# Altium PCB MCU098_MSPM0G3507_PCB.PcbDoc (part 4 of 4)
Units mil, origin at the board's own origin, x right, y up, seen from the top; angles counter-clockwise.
Board outline 2310.03 x 4205.03 mil, 4 copper layers (Top Layer, VCC Layer, GND Layer, Bottom Layer), stack 62.4 mil thick; 260 components, 182 nets, 835 pads, 237 vias.
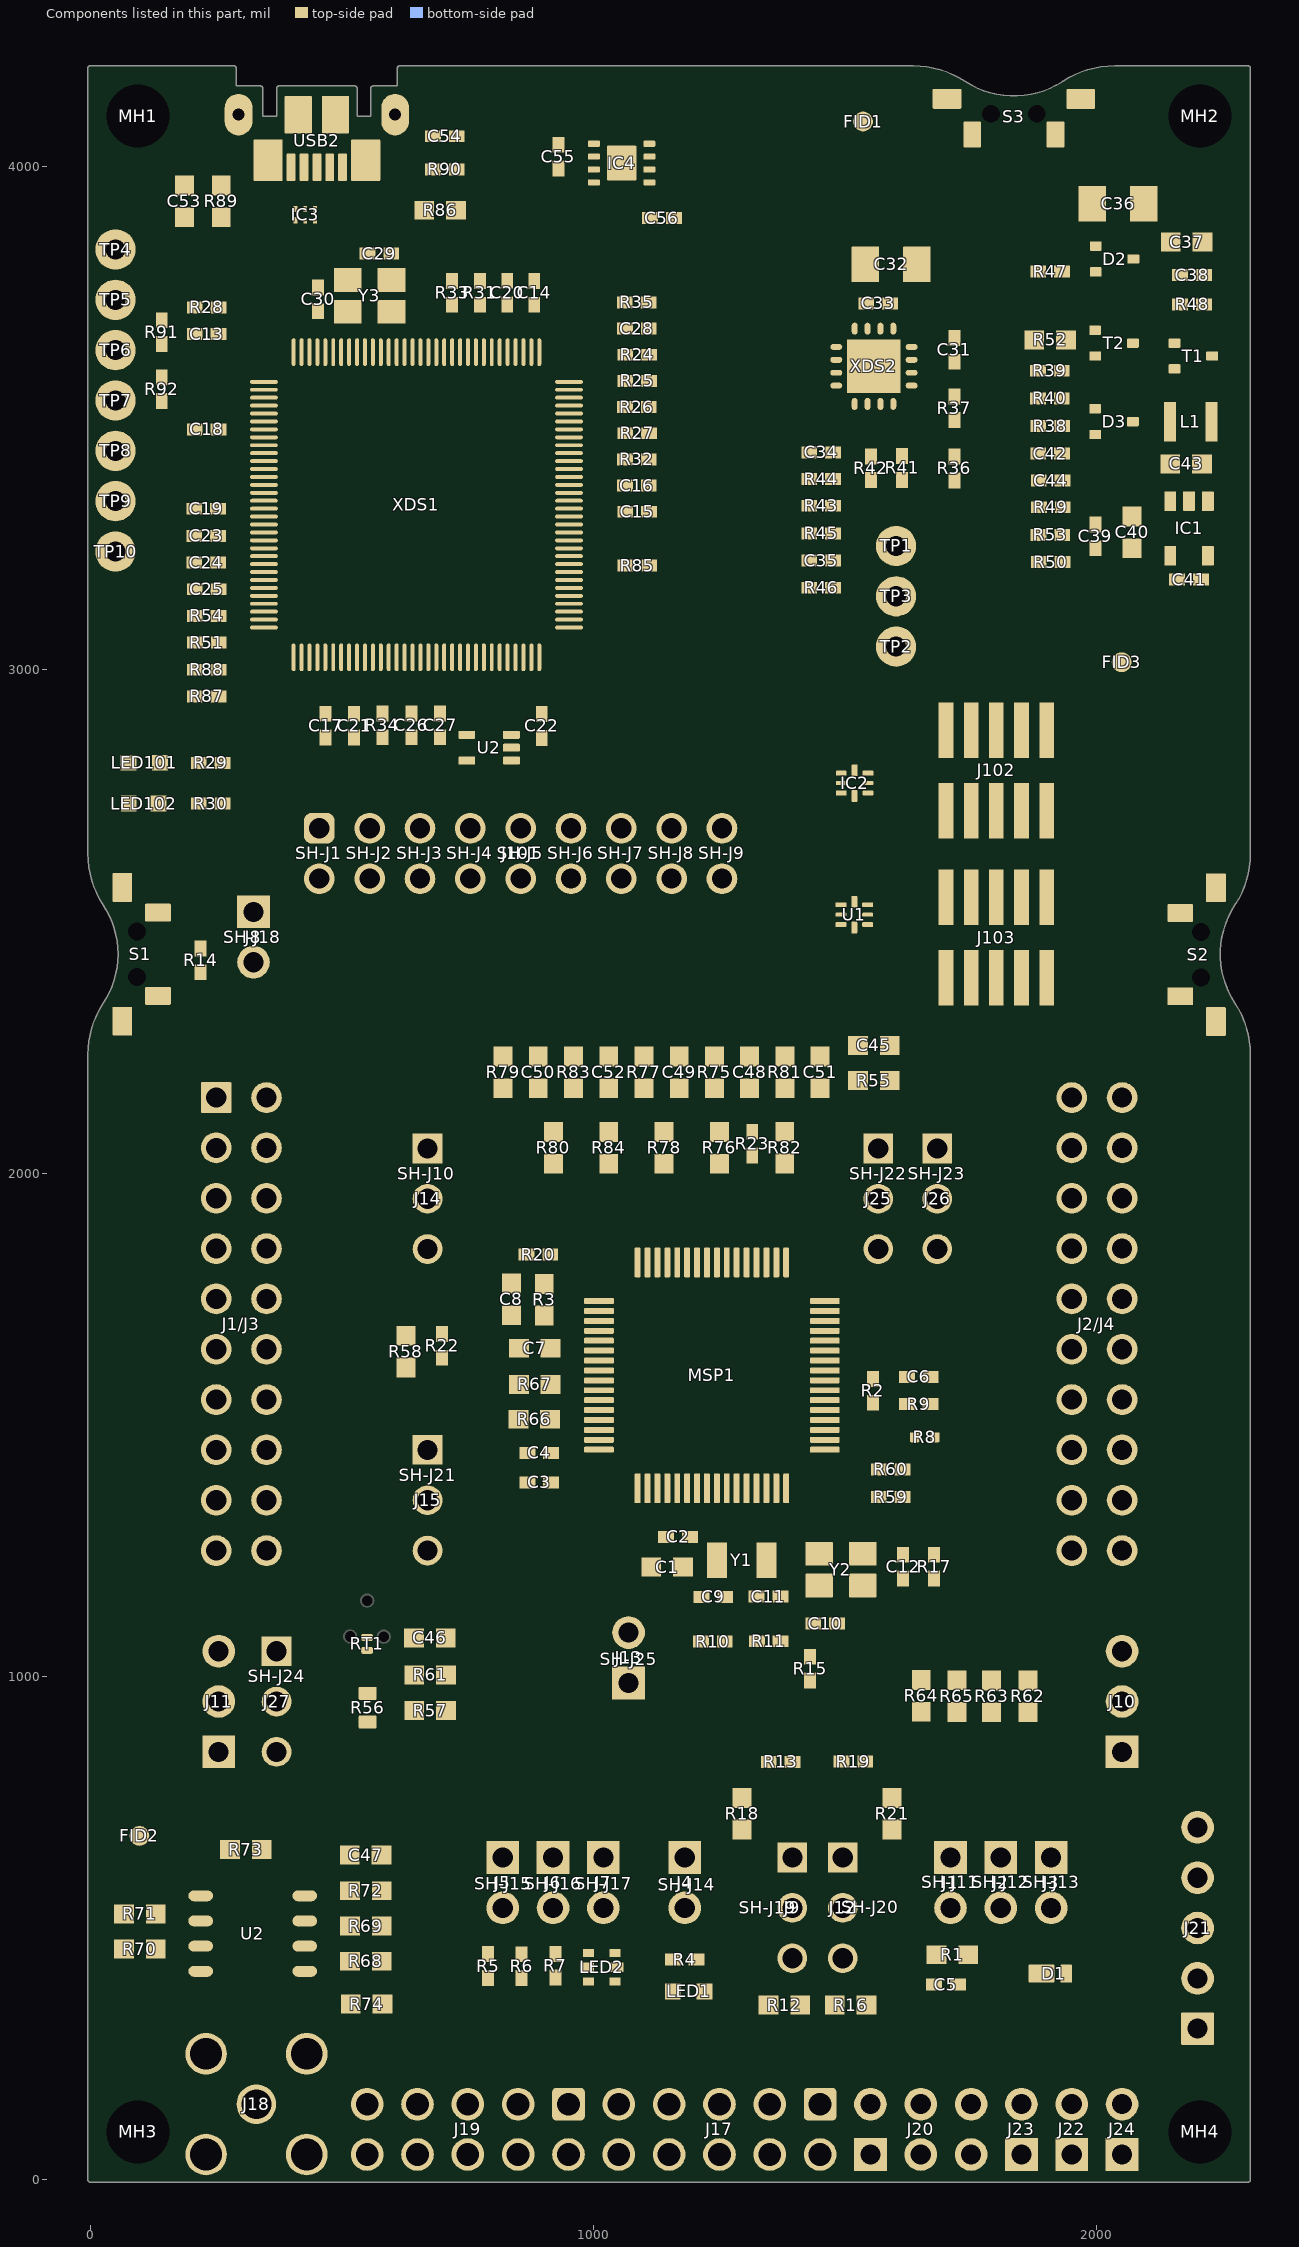
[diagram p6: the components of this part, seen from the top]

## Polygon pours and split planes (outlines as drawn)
GND on Top Layer "TOP_LAYER_GND_P034" (solid, remove dead copper, pour order 34): 0,2635 2300,2635 2300,0 713,0 713,780.96 0.04,780.96 0,781
XDS_GND on Top Layer "TOP_LAYER_XDS_GND_P010" (solid, remove dead copper, pour order 10): -6,4201 2306,4201 2306,2635 -6,2635
GND on Top Layer "TOP_LAYER_GND_P022" (solid, remove dead copper, pour order 22): 0,760 689.04,760 689.12,100.84 490.16,100.84 490.16,0.16 0.16,0.16
XDS_VCC on Top Layer "TOP_LAYER_XDS_VCC_P004" (solid, pour order 4): 1140,3985 1230,3985 1230,3845 1140,3845
GND on GND Layer "GND_LAYER_GND_P030" (solid, remove dead copper, pour order 30): 0,2635 2300,2635 2300,0 713,0 713,780.96 712.96,781 0,781
GND on GND Layer "GND_LAYER_GND_P026" (solid, remove dead copper, pour order 26): 0,760 689.12,760 689.12,100.84 688.28,100 490.16,100 490.16,0.16 0.08,0.08
XDS_GND on GND Layer "GND_LAYER_XDS_GND_P008" (solid, remove dead copper, pour order 8): -6,4201 2306,4201 2306,2635 -6,2635
3V3 on VCC Layer "VCC_LAYER_3V3_P032" (solid, remove dead copper, pour order 32): 810.03,781 810.03,1979.03 809.53,1979.53 1670,1979.53 1670,200 1799,200 1800,199 1800,0 2300,0 2300,2635 0,2635 0,781
GND on VCC Layer "VCC_LAYER_GND_P024" (solid, remove dead copper, pour order 24): 0,760 689.12,760 689.12,100.84 490.16,100.84 490.16,0.16 0,0
XDS_VCC on VCC Layer "GND_LAYER_GND_P-001" (solid, remove dead copper, pour order 38): 0,4195 2300,4195 2300,2635 0,2635
GND on Bottom Layer "BOTTOM_LAYER_GND_P036" (solid, remove dead copper, pour order 36): 0,2635 2300,2635 2300,0 713,0 713,780.96 0.04,780.96 0,781
GND on Bottom Layer "BOTTOM_LAYER_GND_P028" (solid, remove dead copper, pour order 28): 0,760 689.04,760 689.12,100.84 490.16,100.84 490.16,0.16 0,0
XDS_GND on Bottom Layer "BOTTOM_LAYER_XDS_GND_P014" (solid, remove dead copper, pour order 14): -6,4201 2306,4201 2306,2635 -6,2635

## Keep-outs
Keep-Out Layer:
  text ".Layer_Name" at 527,-1523.49 h30

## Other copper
Top Layer:
  pour cut-out: 1066.51,2005.88 1067.52,2006.9 1104.3,2006.9 1104.3,1894.73 1063.1,1853.53
  pour cut-out: 599.99,780.96 631.47,780.96 677.87,827.37 677.87,827.94 737.66,827.94 866.42,956.69 866.42,996.4 868.17,998.16 823.34,998.16 823.34,988.24 753.6,918.5 728.84,918.5 676.81,904.46 675.54,905.73 600.68,905.73
  pour cut-out: 406.6,814.25 400.92,814.25 391.03,824.14 420,853.11 432.79,853.11 499.14,919.47 505.79,919.47
  pour cut-out: 433,934 437.31,923.5 444.47,910.24 468.2,933.97 468.29,933.97
  pour cut-out: 583,1175.1 611.47,1175.1 611.47,1109.2 607.54,1109.2
  pour cut-out: 1849,494.1 1963.28,492.42 1962.43,359.5 1849,359.5
  pour cut-out: 1928.42,2326 1928.42,2484 1727.58,2484 1727.58,2326
  pour cut-out: 1928.42,2656 1928.42,2814 1727.58,2814 1727.58,2656
  pour cut-out: 1447,1156.65 1480.53,1156.65 1481.53,1157.65 1481.53,1030.39 1455.14,1004 1444.88,1004
  pour cut-out: 1689.03,1245.54 1689.49,1246 1689.49,1201.49 1687,1199 1512.84,1199 1508.34,1203.5 1508.34,1245.54
  pour cut-out: 939,373 952.81,373 952.81,362 951.81,363 939.14,363
  pour cut-out: 1014.63,379 1047.36,379 1048,378.36 1048,359 1015.63,359 1014.63,360
  pour cut-out: 1625.8,645.8 1636.86,645.8 1668.06,677 1675,670.06 1673,359.34 1631.34,359.34
  pour cut-out: 711.62,1561.3 732.32,1555.67 753.51,1551.54 746.51,1254.51 745,1253 736.13,1261.87 705,1261.87
  pour cut-out: 1280.41,1262.5 1307.97,1262.5 1306.72,1261.24 1306.72,1178.57 1280.07,1178.57 1280,1178.5 1280,1262.08
  pour cut-out: 1891.63,1965.67 1678.64,1752.68 1678.64,1731.36 1690.89,1719.11 1819.11,1719.11 1950,1850 1950,1939.79
  pour cut-out: 1699.39,1889.25 1717.69,1870.94 1717.69,1869.87 1728.96,1869.87 1953.5,2094.41 1952.4,2095.5 1952.4,2114.25 1933.37,2114.25 1930.62,2117
  pour cut-out: 882.87,1415.19 899.59,1415.19 899.59,1414.08 882.87,1414.08
  pour cut-out: 882.87,1415.19 899.59,1415.19 899.59,1414.08 882.87,1414.08
  pour cut-out: 612.37,511 620.78,511 621,510.78 621,468.29 612.37,468.29
  text ".Layer_Name" at 527,-1523.49 h30
VCC Layer:
  pour cut-out: 624.77,811.49 624.77,781.87 623.86,780.96 599.99,780.96
  pour cut-out: 561,811.49 561,780.87 561.09,780.96 576.33,780.96
  text ".Layer_Name" at 527,-1523.49 h30
GND Layer:
  pour cut-out: 560.84,808.35 560.84,781.15 561,781 561.7,781.71 575.08,781.71
  text ".Layer_Name" at 527,-1523.49 h30
Bottom Layer:
  pour cut-out: 741.57,1030.47 741.57,970.96 752.17,960.36 775.18,983.37 834.16,983.37 834.16,995.31 797.72,1031.75
  pour cut-out: 548,1233 548,1195.91 595.47,1195.91 573.5,1217.88 573.5,1220.09
  pour cut-out: 624.77,811.49 624.77,780.96 599.99,780.96
  pour cut-out: 560.84,808.35 560.84,781.15 561.04,780.96 576.33,780.96
  text ".Layer_Name" at 527,-1523.49 h30

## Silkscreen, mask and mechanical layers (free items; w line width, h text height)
Top Overlay:
  drawing of 1933 lines, arcs and shapes, not listed
  text "MSP NRST" at 1606.35,3946.95 h40
  text "Rev. A" at 2264.13,2813.42 h60 r90
  text "XDS110-ET Debug Probe" at 428.03,2753 h30
  text "Rev1.4" at 1158,2747 h30
  text "XDS110 Out" at 1650.72,2668 h30 r90
  text "LP-MSPM0G3507" at 2205.15,2665.28 h65 r90
  text "(PB21)" at 1946.02,2381.37 h40
  text "BSL" at 1277.43,2376.37 h40 r90
  text "NRST" at 980,2358 h40 r90
  text "SWDIO" at 1074.13,2342 h40 r90
  text "SWCLK" at 1169.54,2342 h40 r90
  text "RXD<<" at 775,2340 h40 r90
  text "TXD>>" at 875,2340 h40 r90
  text "XDS110 In" at 1647,2340.5 h30 r90
  text "(PA18)" at 240.75,2280.75 h40
  text "PB4" at 1750,2130 h60
  text "PB4" at 1750.21,2130 h60
  text "XDS" at 1404.48,2031.35 h60
  text "PA25" at 50,2030 h60
  text "PB1" at 1750,2030 h60
  text "PB12" at 2160,2030 h60
  text "PB23" at 735.69,2027 h60
  text "SW1" at 50,1930 h60
  text "PB19" at 460,1930 h60
  text "PA28" at 1750,1930 h60
  text "PB17" at 2160,1930 h60
  text "SW1" at 751.47,1927.61 h60
  text "UART" at 1479.2,1899.56 h50 r90
  text "MSPM0G3507" at 1075.32,1867.37 h50
  text "BP" at 1440.73,1834.22 h60
  text "PA8" at 50,1830 h60
  text "PA22" at 460,1830 h60
  text "PA9" at 735,1830 h60
  text "PA31" at 1750,1830 h60
  text "PB15" at 2160,1830 h60
  text "PA26" at 50,1730 h60
  text "PB18" at 460,1730 h60
  text "PB20" at 1750,1730 h60
  text "NRST" at 2160,1730 h60
  text "PB24" at 50,1630 h60
  text "PA18" at 460,1630 h60
  text "PB13" at 1750,1630 h60
  text "PB8" at 2160,1630 h60
  text "PB9" at 50,1530 h60
  text "PA24" at 460,1530 h60
  text "PA10" at 1750,1530 h60
  text "PB7" at 2160,1530 h60
  text "PA27" at 50,1430 h60
  text "PA17" at 460,1430 h60
  text "PA11" at 1750,1430 h60
  text "PB6" at 2160,1430 h60
  text "PB2" at 50,1330 h60
  text "SW2" at 460,1330 h60
  text "PA12" at 1750,1330 h60
  text "PB0" at 2160,1330 h60
  text "PA16" at 818.4,1296 h60
  text "SW2" at 818,1238 h60
  text "PB3" at 50,1230 h60
  text "PA15" at 460,1230 h60
  text "PA13" at 1750,1230 h60
  text "PB16" at 2160,1230 h60
  text "PA18" at 819,1180 h60
  text "Thermistor" at 633.72,1110 h60
  text "PB24" at 467,993.43 h60 r90
  text "A.PWR" at 1005.13,939.83 h60 r90
  text "PA26" at 468.29,791 h60 r90
  text "PA22" at 1700.04,779.62 h60 r45
  text "PA27" at 1800,780 h60 r45
  text "PA26" at 1900,779 h60 r45
  text "PB22" at 786.74,775.84 h60 r45
  text "PA0" at 1160.62,775 h60 r45
  text "PB27" at 985.59,774 h60 r45
  text "PB26" at 887.2,773 h60 r45
  text "OPA2365" at 200,702.38 h60
  text "3V" at 1263.78,611 h60
  text "3V" at 1561.78,611 h60
  text "5V" at 1264.78,423.62 h60
  text "5V" at 1560.78,422.62 h60
  text "QEI Interface" at 2125.72,310.72 h80 r90
  text "B25" at 610,260 h50
  text "B11" at 809.84,260 h50
  text "B5" at 923.84,260 h50
  text "A14" at 1109.62,260 h50
  text "A6" at 1223,260 h50
  text "A4" at 1322,259.58 h50
  text "A2" at 1418,260 h50
  text "GND" at 1501,260.16 h50
  text "GND" at 1603.72,260.16 h50
  text "A11" at 1708,260 h50
  text "A0" at 522.4,258.56 h50
  text "B22" at 709.84,259 h50
  text "A1" at 1024,258.56 h50
  text "GND" at 2004,236 h50
  text "5V" at 1825.92,234 h50
  text "3V3" at 1908.5,234 h50
  text "B27" at 509.84,209.66 h50
  text "B26" at 609.84,209.66 h50
  text "B23" at 710,209.66 h50
  text "B21" at 810,210 h50
  text "B10" at 910,209.67 h50
  text "A23" at 1009.84,210 h50
  text "A21" at 1110.13,210 h50
  text "A7" at 1223,210 h50
  text "A5" at 1322,210 h50
  text "A3" at 1418,210 h50
  text "A12" at 1500,210 h50
  text "A13" at 1606.03,210 h50
  text "A10" at 1708,210 h50
  text ".Layer_Name" at 527,-1523.49 h30
Bottom Overlay:
  drawing of 24769 lines, arcs and shapes, not listed
  text "PB4" at 1868.21,2129.3 h60
  text "PA25" at 145.94,2030.07 h60
  text "PB1" at 1868,2029.3 h60
  text "PB12" at 2278,2029.3 h60
  text "SW1" at 145.94,1930.07 h60
  text "PB19" at 555.94,1930.07 h60
  text "PA28" at 1868,1929.3 h60
  text "PB17" at 2278,1929.3 h60
  text "PA8" at 145.94,1830.07 h60
  text "PA22" at 555.94,1830.07 h60
  text "PA31" at 1868,1829.3 h60
  text "PB15" at 2278,1829.3 h60
  text "PA26" at 145.94,1730 h60
  text "PB18" at 555.94,1730.07 h60
  text "PB20" at 1868,1729.3 h60
  text "NRST" at 2278,1729.3 h60
  text "PB24" at 145.94,1630 h60
  text "PA18" at 555.94,1630.07 h60
  text "PB13" at 1868,1629.3 h60
  text "PB8" at 2278,1629.3 h60
  text "PB9" at 145.94,1530.07 h60
  text "PA24" at 555.94,1530.07 h60
  text "PA10" at 1868,1529.3 h60
  text "PB7" at 2278,1529.3 h60
  text "PA27" at 145.94,1430.07 h60
  text "PA17" at 555.94,1430.07 h60
  text "PA11" at 1868,1429.3 h60
  text "PB6" at 2278,1429.3 h60
  text "PB2" at 145.94,1330.07 h60
  text "SW2" at 555.94,1330.07 h60
  text "PA12" at 1868,1329.3 h60
  text "PB0" at 2278,1329.3 h60
  text "PB3" at 145.94,1230.07 h60
  text "PA15" at 555.94,1230.07 h60
  text "PA13" at 1868,1229.3 h60
  text "PB16" at 2278,1229.3 h60
  text "GND" at 2128,682.97 h60
  text "3V3" at 2128,582.97 h60
  text "PB14" at 2128,481.97 h60
  text "PA30" at 2128,382.97 h60
  text "PA29" at 2128,282.97 h60
  text ".Layer_Name" at 527,-1523.49 h30
Top Paste:
  text ".Layer_Name" at 527,-1523.49 h30
Bottom Paste:
  text ".Layer_Name" at 527,-1523.49 h30
Top Solder:
  text ".Layer_Name" at 527,-1523.49 h30
  text ".Layer_Name" at 527,-1523.49 h30
Bottom Solder:
  text ".Layer_Name" at 527,-1523.49 h30
Drill Guide:
  text ".Layer_Name" at 527,-1523.49 h30
M1 Board Outline:
  lines w10: 0,0 0,2235 ; 0,0 2300,0 ; 0,0 2300,0 ; 0,0 0,2235 ; 0,2235 cw(c181.67,2235) 30,2335 ; 0,2235 cw(c181.67,2235) 30,2335 ; 0,2635 ccw(c181.67,2635) 30,2535 ; 0,2635 ccw(c181.67,2635) 30,2535 ; 0,2635 0,4195 ; 0,2635 0,4195 ; 0,4195 285,4195 ; 0,4195 285,4195 ; 30,2335 ccw(c-121.67,2435) 30,2535 ; 30,2335 ccw(c-121.67,2435) 30,2535 ; 30,2535 30,2535 ; 285,4155 338,4155 ; 285,4155 285,4195 ; 285,4155 285,4195 ; 285,4155 338,4155 ; 338,4095 375,4095 ; 338,4095 338,4155 ; 338,4095 338,4155 ; 338,4095 375,4095 ; 375,4095 375,4155 ; 375,4095 375,4155 ; 375,4155 525,4155 ; 375,4155 525,4155 ; 525,4095 562,4095 ; 525,4095 525,4155 ; 525,4095 525,4155 ; 525,4095 562,4095 ; 562,4095 562,4155 ; 562,4095 562,4155 ; 562,4155 615,4155 ; 562,4155 615,4155 ; 615,4155 615,4195 ; 615,4155 615,4195 ; 615,4195 1635,4195 ; 615,4195 1635,4195 ; 1635,4195 cw(c1635,4013.33) 1735,4165 ; 1635,4195 cw(c1635,4013.33) 1735,4165 ; 1735,4165 ccw(c1835,4316.67) 1935,4165 ; 1735,4165 ccw(c1835,4316.67) 1935,4165 ; 1935,4165 cw(c2035,4013.33) 2035,4195 ; 1935,4165 cw(c2035,4013.33) 2035,4195 ; 1935,4165 1935,4165 ; 2035,4195 2300,4195 ; 2035,4195 2300,4195 ; 2270,2335 cw(c2118.33,2235) 2300,2235 ; 2270,2335 cw(c2421.67,2435) 2270,2535 ; 2270,2335 cw(c2421.67,2435) 2270,2535 ; 2270,2335 cw(c2118.33,2235) 2300,2235 ; 2270,2335 2270,2335 ; 2270,2535 ccw(c2118.33,2635) 2300,2635 ; 2270,2535 ccw(c2118.33,2635) 2300,2635 ; 2300,0 2300,2235 ; 2300,0 2300,2235 ; 2300,2635 2300,4195 ; 2300,2635 2300,4195
  text ".Layer_Name" at 527,-1523.49 h30
M2 Board Dimensions:
  rectangle: 75,-1065 450,-940
  rectangle: -50,-940 75,-815
  lines w7: -50,-940 950,-940 ; 75,-1065 75,-815 ; 200,-1065 200,-815 ; 450,-1065 450,-815 ; 700,-1065 700,-815 ; -50,-1065 -50,-815 950,-815 950,-1065 -50,-1065
  lines w10: 1711,4198.98 1711,4256.98 1917,4462.98 1987.5,4462.98 ; 1835,4160.98 1835,4278.98 1919,4362.98 1995,4362.98 ; 1955,4198.98 1955,4252.98 1980,4277.98 1995,4277.98 ; 1980,4462.98 1995,4462.98 ; 2350,4197.98 2375,4222.98 2375,4512.98 2350,4537.98
  text "Radius 180" at 2015,4437.98 h30
  text "Radius 180" at 2015,4342.98 h30
  text "3 Places" at 2450,4340 h30
  text "Radius 180" at 2015,4252.98 h30
  text ".Layer_Name" at 527,-1523.49 h30
M3 3D STEP Top:
  text ".Layer_Name" at 527,-1523.49 h30
M4 3D STEP Bottom:
  text ".Layer_Name" at 527,-1523.49 h30
M5 Assembly Top:
  circle w6: c1382.04,1872 r5.83
  lines w10: -342,-1595.17 6258,-1595.17 ; -342,-1391.83 6260,-1391.83 ; -342,-1188.5 -342,-1798.5 3663,-1798.5 6260,-1798.5 6260,-1188.5 -341.5,-1188.5 -341.5,-1798.5 1234,-1798.5 ; 2123,-1798.5 2123,-1188.5 ; 3390,-1391.83 3390,-1188.5 ; 4230,-1391.83 4230,-1188.5 ; 4852,-1805 4852,-1602.17
  text "COMPONENTS MARKED 'DNP' SHOULD NOT BE POPULATED." at 1103.5,-983.5 h30
  text "ASSEMBLY VARIANT:" at 1103,-1099 h30
  text ".VariantName" at 2139,-1099 h30
  text "PCB VIEWED FROM TOP SIDE" at -278.5,-1320.67 h30
  text "BOARD #:" at 2198,-1320.67 h30
  text ".PRJ_Number" at 2743.5,-1320.67 h30
  text "REV:" at 3588,-1320.67 h30
  text ".PCB_Rev" at 3879.5,-1320.67 h30
  text "SVN REV:" at 4426,-1320.67 h30
  text ".VersionControl_RevNumber" at 4932,-1320.67 h30
  text "TID #:" at 2198,-1524 h30
  text ".TID" at 2743.5,-1524 h30
  text "PLOT NAME =" at -278.5,-1729.34 h30
  text ".plot_File_Name" at 527,-1729.34 h30
  text "GENERATED    :" at 2200,-1729.34 h30
  text ".Print_Date" at 3069.5,-1729.34 h30
  text ".Print_Time" at 3798.5,-1729.34 h30
  text "TEXAS INSTRUMENTS" at 5063,-1729.34 h30
M6 Assembly Bottom:
  lines w10: -342.5,-1392.33 6259.5,-1392.33 ; -340.5,-1595.67 6259.5,-1595.67 ; 1065.5,-1805.5 1065.5,-1602.67 ; 1687.5,-1392.33 1687.5,-1189 ; 2527.5,-1392.33 2527.5,-1189 ; 3794.5,-1799 3794.5,-1189 ; 4683.5,-1799 6259,-1799 6259,-1189 -342.5,-1189 -342.5,-1799 2254.5,-1799 6259.5,-1799 6259.5,-1189
  text "COMPONENTS MARKED 'DNP' SHOULD NOT BE POPULATED." at 6052,-983 h30
  text ".VariantName" at 5008,-1099 h30
  text "ASSEMBLY VARIANT:" at 6047,-1099 h30
  text ".VersionControl_RevNumber" at 985.5,-1321.17 h30
  text "SVN REV:" at 1491.5,-1321.17 h30
  text ".PCB_Rev" at 2038,-1321.17 h30
  text "REV:" at 2329.5,-1321.17 h30
  text ".PRJ_Number" at 3174,-1321.17 h30
  text "BOARD #:" at 3719.5,-1321.17 h30
  text "PCB VIEWED FROM BOTTOM SIDE" at 6196,-1321.17 h30
  text ".TID" at 3174,-1524.5 h30
  text "TID #:" at 3719.5,-1524.5 h30
  text "TEXAS INSTRUMENTS" at 854.5,-1729.84 h30
  text ".Print_Time" at 2119,-1729.84 h30
  text ".Print_Date" at 2848,-1729.84 h30
  text "GENERATED    :" at 3717.5,-1729.84 h30
  text ".plot_File_Name" at 5390.5,-1729.84 h30
  text "PLOT NAME =" at 6196,-1729.84 h30
M9 Title Sheet:
  drawing of 57 lines, arcs and shapes, not listed
  text "1" at 689.84,7371.5 h30
  text "2" at 3185.5,7371.5 h30
  text "3" at 5674.84,7371.5 h30
  text "4" at 8181.51,7371.5 h30
  text "5" at 10680.5,7371.5 h30
  text "6" at 13185.5,7371.5 h30
  text "A" at -466.5,6228.5 h30
  text "A" at 14333.5,6228.5 h30
  text "B" at -466.5,3848.5 h30
  text "B" at 14333.5,3848.5 h30
  text "C" at -466.5,1473.5 h30
  text "C" at 14333.5,1473.5 h30
  text "PROJECT TITLE:" at 11293.5,-387.5 h30
  text ".PRJ_Title" at 11343.5,-520.83 h30
  text "DESIGNED FOR:" at 11293.5,-688.5 h30
  text ".PRJ_Customer" at 11343.5,-828.5 h30
  text "D" at -466.5,-896.5 h30
  text "D" at 14333.5,-896.5 h30
  text "FILE NAME:" at 11293.5,-988.5 h30
  text ".PCB_File_Name_No_Path" at 11343.5,-1108.5 h30
  text "Texas Instruments (TI) and/or its licensors do not warrant the accuracy or completeness of this specification" at 6324,-1270.34 h30
  text "ENGINEER:" at 11293.5,-1278.5 h30
  text "LAYOUT BY:" at 12798.5,-1278.5 h30
  text "or any information contained therein. TI and/or its licensors do not warrant that this design will meet" at 6279.01,-1383 h30
  text ".PRJ_Engineer" at 11343.5,-1433.49 h30
  text ".PCB_Layout" at 12849,-1433.49 h30
  text "the specifications, will be suitable for your application or fit for any particular purpose, or will operate in" at 6279.01,-1495.67 h30
  text ".Layer_Name" at 527,-1523.49 h30
  text "ALTIUM DESIGNER VERSION:" at 12798.5,-1588.5 h30
  text "an implementation. TI and/or its licensors do not warrant that the design is production worthy. You should" at 6279.01,-1608.33 h30
  text "completely validate and test your design implementation to confirm the system functionality for your application." at 6324,-1721 h30
  text ".print_Scale" at 11343.5,-1721.83 h30
  text ".Application_BuildNumber" at 12849,-1721.83 h30
  text "1" at 689.84,-1928.5 h30
  text "2" at 3185.5,-1928.5 h30
  text "3" at 5674.84,-1928.5 h30
  text "4" at 8181.51,-1928.5 h30
  text "5" at 10680.5,-1928.5 h30
  text "6" at 13185.5,-1928.5 h30
M10 Fab Notes:
  drawing of 173 lines, arcs and shapes, not listed
  text "DESIGN INFORMATION" at 12328.02,5536 h30
  text "MIN. TRACK WIDTH:" at 11683.46,5356 h30
  text "8" at 12779.7,5356 h30
  text "MIL" at 12934.46,5356 h30
  text "MIN. CLEARANCE:" at 11683.46,5224 h30
  text "0.2" at 12719.7,5224 h30
  text "mm" at 12934.46,5224 h30
  text "MIN. VIA PAD SIZE:" at 11683.46,5092 h30
  text "24" at 12749.71,5092 h30
  text "MIL" at 12934.46,5092 h30
  text "0.05mm (2MIL)" at 12378.46,4950.29 h30
  text "MINIMUM ANNULAR RING" at 11354.23,4946 h30
  text "EXTERNAL" at 13086.46,4946 h30
  text "PER" at 11554.23,4828 h30
  text "IPC-D-275 CLASS 2 LEVEL C" at 11774.23,4828 h30
  text "MIL, HOLES" at 13262.46,4715.71 h30
  text "+/-" at 12870,4715 h30
  text "+/-" at 13724,4715 h30
  text "REGISTRATION TOLERANCES:" at 11354.23,4710 h30
  text "METAL" at 12554,4710 h30
  text "5" at 13130.2,4710 h30
  text "3" at 13963.2,4710 h30
  text "MIL" at 14079.46,4710 h30
  text "+/-" at 13724,4597 h30
  text "HOLE SIZE TOLERANCE (UNLESS OTHERWISE SPECIFIED):" at 11354.23,4592 h30
  text "3" at 13963.2,4592 h30
  text "MIL" at 14079.46,4592 h30
  text "MATERIAL:" at 11279.46,4382.54 h30
  text "FR-4 High Tg" at 12265.9,4242.21 h30
  text "FR-408" at 11700.46,4233.64 h30
  text "OTHER" at 13188.46,4233.64 h30
  text "X" at 12111,4230 h30
  text "62 MIL (1.6mm) +/-10%" at 12020.56,4070.92 h30
  text "THICKNESS:" at 11354.23,4066.64 h30
  text "X" at 11892.4,4066.64 h30
  text "OTHER" at 13305.46,4066.64 h30
  text "TOLERANCE:" at 11354.23,3908.64 h30
  text "X" at 12193.53,3908.64 h30
  text "ANSI IPC-6012 TYPE 3 CLASS 2" at 12380.48,3908.64 h30
  text "OTHER +/-" at 12380.46,3752.64 h30
  text "BOW & TWIST:" at 11354.23,3595.64 h30
  text "X" at 12193.53,3595.64 h30
  text "ANSI IPC-6012 TYPE 3 CLASS 2" at 12380.48,3595.64 h30
  text "OTHER +/-" at 12380.46,3437.13 h30
  text "DRILLING:" at 11279.46,3298.64 h30
  text "REFERENCE:" at 11354.23,3181.64 h30
  text "X" at 12002.46,3181.64 h30
  text "AS SHOWN" at 12189.46,3181.64 h30
  text "X" at 12903.46,3181.64 h30
  text "NC_DRILL FILES" at 13040.46,3181.64 h30
  text "PTH COPPER THICKNESS:" at 11354.23,3023.64 h30
  text "X" at 12484.46,3023.64 h30
  text "20-30 um" at 12621.46,3023.64 h30
  text "OTHER" at 13338.46,3023.64 h30
  text "BOARD FINISH:" at 11279.46,2864.64 h30
  text "SILKSCREEN:" at 11434.68,2746.64 h30
  text "X" at 12383.46,2746.64 h30
  text "TOP" at 12509.46,2746.64 h30
  text "X" at 12893.46,2746.64 h30
  text "BOTTOM" at 13020.46,2746.64 h30
  text "SILKSCREEN COLOR:" at 11434.68,2579.64 h30
  text "X" at 12382.42,2579.64 h30
  text "WHITE" at 12509.46,2579.64 h30
  text "OTHER" at 13020.46,2579.64 h30
  text "GREEN" at 12640.46,2420.44 h30
  text "X" at 13105,2420 h30
  text "OTHER" at 13258.46,2420.44 h30
  text "Red" at 13655,2420 h30
  text "SOLDER RESIST COLOR:" at 11434.68,2409.64 h30
  text "X" at 12513.42,2250.44 h30
  text "MATTE" at 12640.46,2250.44 h30
  text "SEMI-GLOSS" at 13258,2249.8 h30
  text "IMMERSION GOLD (ENIG)" at 12340.46,2061.92 h30
  text "ENEPIG" at 13678,2058.64 h30
  text "SURFACE FINISH:" at 11279.46,2057.64 h30
  text "IMM. TIN/SILVER OR EQUIV" at 11609,1900.64 h30
  text "OTHER" at 13040.46,1900.64 h30
  text "X" at 11445,1900 h30
  text "ARRAY/PANEL:" at 11279.46,1721.64 h30
  text "CUT AND TRIM PER M1 BOARD OUTLINE" at 12340.46,1717.35 h30
  text "N.C. ROUTE" at 12340.46,1565.64 h30
  text "X" at 13019.46,1565.64 h30
  text "V. SCORE" at 13206.46,1565.64 h30
  text "CERTIFICATION:" at 11279.46,1428.64 h30
  text "MATERIALS AND WORKMANSHIP FOR ALL PCBS" at 12004.46,1428.64 h30
  text "TO MEET OR EXCEED THE REQUIREMENTS OF:" at 12004.46,1330.64 h30
  text "X" at 11630.96,1194.13 h30
  text "ANSI IPC-A-600F CLASS ->" at 11769.96,1194.13 h30
  text "X" at 13409.02,1194.13 h30
  text "2" at 13527.96,1194.14 h30
  text "1" at 13212.96,1192.64 h30
  text "3" at 13881.96,1192.64 h30
  text "X" at 12445.02,1034.64 h30
  text "RoHS" at 12581.96,1034.64 h30
  text "OTHER" at 13226.36,1034.64 h30
  text "PER ORDER" at 13623.42,1034.64 h30
  text "ALL BOARDS MUST MEET OR EXCEED UL94-V0 REQUIREMENTS." at 11307,869 h30
  text "PCB MUST BEAR THE UL94V-0 UL REGISTERED MATERIAL ID NUMBER" at 11307,749 h30
  text "ADDITIONAL REQUIREMENTS:" at 11279.46,575.64 h30
  text "MICROSECTION:" at 11354.23,460.64 h30
  text "YES" at 12259.96,460.64 h30
  text "X" at 13585,305 h30
  text "REQUIRED" at 13121.46,304.49 h30
  text "BARE BOARD ELEC. TEST:" at 11354.23,301.64 h30
  text "NONE" at 12659.96,301.64 h30
  text "PER ORDER" at 13713.46,301.64 h30
  text ".Layer_Name" at 527,-1523.49 h30
M11 Gerber Information:
  lines w10: -342,-1595.17 6258,-1595.17 ; -342,-1391.83 6260,-1391.83 ; -342,-1188.5 -342,-1798.5 3663,-1798.5 6260,-1798.5 6260,-1188.5 -341.5,-1188.5 -341.5,-1798.5 1234,-1798.5 ; 2123,-1798.5 2123,-1188.5 ; 3390,-1391.83 3390,-1188.5 ; 4230,-1391.83 4230,-1188.5 ; 4852,-1805 4852,-1602.17
  text "ALL ARTWORK VIEWED FROM TOP SIDE" at -278.5,-1320.67 h30
  text "BOARD #:" at 2198,-1320.67 h30
  text ".PRJ_Number" at 2743.5,-1320.67 h30
  text "REV:" at 3588,-1320.67 h30
  text ".PCB_Rev" at 3879.5,-1320.67 h30
  text "SVN REV:" at 4426,-1320.67 h30
  text ".VersionControl_RevNumber" at 4932,-1320.67 h30
  text "LAYER NAME =" at -278.5,-1523.49 h30
  text "TID #:" at 2198,-1524 h30
  text ".TID" at 2743.5,-1524 h30
  text "PLOT NAME =" at -278.5,-1729.34 h30
  text ".plot_File_Name" at 527,-1729.34 h30
  text "GENERATED    :" at 2200,-1729.34 h30
  text ".Print_Date" at 3069.5,-1729.34 h30
  text ".Print_Time" at 3798.5,-1729.34 h30
  text "TEXAS INSTRUMENTS" at 5063,-1729.34 h30
M12 Stackup:
  drawing of 295 lines, arcs and shapes, not listed
  text "Layer" at 8591.29,5576 h30
  text "Name" at 8806.24,5576 h30
  text "Material" at 9281.12,5576 h30
  text "Thickness" at 9571.05,5576 h30
  text "Constant" at 9905.97,5576 h30
  text "Board Layer Stack" at 10200.9,5576 h30
  text "1" at 8591.29,5516 h30
  text "Top Overlay" at 8806.24,5516 h30
  text "2" at 8591.29,5456 h30
  text "Top Solder" at 8806.24,5456 h30
  text "SM-004" at 9281.12,5456 h30
  text "0.98mil" at 9571.05,5456 h30
  text "4" at 9905.97,5456 h30
  text "3" at 8591.29,5396 h30
  text "Top Layer" at 8806.24,5396 h30
  text "Copper" at 9281.12,5396 h30
  text "1.40mil" at 9571.05,5396 h30
  text "4" at 8591.29,5336 h30
  text "Dielectric 2" at 8806.24,5336 h30
  text "FR-4" at 9281.12,5336 h30
  text "8.40mil" at 9571.05,5336 h30
  text "4.2" at 9905.97,5336 h30
  text "5" at 8591.29,5276 h30
  text "VCC Layer" at 8806.24,5276 h30
  text "Copper" at 9281.12,5276 h30
  text "1.40mil" at 9571.05,5276 h30
  text "6" at 8591.29,5216 h30
  text "Dielectric1" at 8806.24,5216 h30
  text "FR-4" at 9281.12,5216 h30
  text "40.00mil" at 9571.05,5216 h30
  text "4.2" at 9905.97,5216 h30
  text "7" at 8591.29,5156 h30
  text "GND Layer" at 8806.24,5156 h30
  text "Copper" at 9281.12,5156 h30
  text "1.40mil" at 9571.05,5156 h30
  text "8" at 8591.29,5096 h30
  text "Dielectric 3" at 8806.24,5096 h30
  text "FR-4" at 9281.12,5096 h30
  text "8.40mil" at 9571.05,5096 h30
  text "4.2" at 9905.97,5096 h30
  text "9" at 8591.29,5036 h30
  text "Bottom Layer" at 8806.24,5036 h30
  text "Copper" at 9281.12,5036 h30
  text "1.40mil" at 9571.05,5036 h30
  text "10" at 8591.29,4976 h30
  text "Bottom Solder" at 8806.24,4976 h30
  text "SM-004" at 9281.12,4976 h30
  text "0.98mil" at 9571.05,4976 h30
  text "4" at 9905.97,4976 h30
  text "11" at 8591.29,4916 h30
  text "Bottom Overlay" at 8806.24,4916 h30
  text ".Layer_Name" at 527,-1523.49 h30
M13 Component Bodies Top:
  text ".Layer_Name" at 527,-1523.49 h30
M14 Component Bodies Bottom:
  text ".Layer_Name" at 527,-1523.49 h30
M15 Courtyards Top:
  text ".Layer_Name" at 527,-1523.49 h30
M16 Courtyards Bottom:
  text ".Layer_Name" at 527,-1523.49 h30
Drill Drawing:
  circle w10: c6074.13,4505.29 r10
  circle w10: c6074.13,4505.29 r16.67
  circle w10: c6074.13,3755.29 r16.67
  lines w10: 6057.46,3813.62 6074.13,3821.95 6090.79,3813.62 6082.46,3830.29 6090.79,3846.95 6074.13,3838.62 6057.46,3846.95 6065.79,3830.29 6057.46,3813.62 ; 6057.46,3888.62 6090.79,3888.62 6090.79,3921.95 6057.46,3921.95 6057.46,3888.62 ; 6057.46,3963.62 6057.46,3971.95 6065.79,3980.29 6057.46,3988.62 6057.46,3996.95 6065.79,3996.95 6074.13,3988.62 6082.46,3996.95 6090.79,3996.95 6090.79,3988.62 6082.46,3980.29 6090.79,3971.95 6090.79,3963.62 6082.46,3963.62 6074.13,3971.95 6065.79,3963.62 6057.46,3963.62 ; 6057.46,4055.29 6074.13,4038.62 6090.79,4055.29 6074.13,4071.95 6057.46,4055.29 ; 6057.46,4121.95 6065.79,4121.95 6065.79,4113.62 6082.46,4113.62 6082.46,4121.95 6090.79,4121.95 6090.79,4138.62 6082.46,4138.62 6082.46,4146.95 6065.79,4146.95 6065.79,4138.62 6057.46,4138.62 6057.46,4121.95 ; 6057.46,4188.62 6074.13,4196.95 6090.79,4188.62 6082.46,4205.29 6090.79,4221.95 6074.13,4213.62 6057.46,4221.95 6065.79,4205.29 6057.46,4188.62 ; 6057.46,4296.95 6090.79,4296.95 6074.13,4263.62 6057.46,4296.95 ; 6057.46,4371.95 6090.79,4371.95 6074.13,4338.62 6057.46,4371.95 ; 6057.46,4421.95 6065.79,4421.95 6074.13,4413.62 6082.46,4421.95 6090.79,4421.95 6082.46,4430.29 6090.79,4438.62 6082.46,4438.62 6074.13,4446.95 6065.79,4438.62 6057.46,4438.62 6065.79,4430.29 6057.46,4421.95 ; 6057.46,4563.62 6057.46,4571.95 6065.79,4580.29 6057.46,4588.62 6057.46,4596.95 6065.79,4596.95 6074.13,4588.62 6082.46,4596.95 6090.79,4596.95 6090.79,4588.62 6082.46,4580.29 6090.79,4571.95 6090.79,4563.62 6082.46,4563.62 6074.13,4571.95 6065.79,4563.62 6057.46,4563.62 ; 6057.46,4638.62 6090.79,4638.62 6090.79,4671.95 6057.46,4671.95 6057.46,4638.62 ; 6064.13,3820.29 6074.13,3825.29 6084.13,3820.29 6079.13,3830.29 6084.13,3840.29 6074.13,3835.29 6064.13,3840.29 6069.13,3830.29 6064.13,3820.29 ; 6064.13,4365.29 6084.13,4365.29 6074.13,4345.29 6064.13,4365.29 ; 6064.13,4425.29 6069.13,4425.29 6074.13,4420.29 6079.13,4425.29 6084.13,4425.29 6079.13,4430.29 6084.13,4435.29 6079.13,4435.29 6074.13,4440.29 6069.13,4435.29 6064.13,4435.29 6069.13,4430.29 6064.13,4425.29 ; 6064.13,4570.29 6064.13,4575.29 6069.13,4580.29 6064.13,4585.29 6064.13,4590.29 6069.13,4590.29 6074.13,4585.29 6079.13,4590.29 6084.13,4590.29 6084.13,4585.29 6079.13,4580.29 6084.13,4575.29 6084.13,4570.29 6079.13,4570.29 6074.13,4575.29 6069.13,4570.29 6064.13,4570.29 ; 6064.13,4645.29 6084.13,4645.29 6084.13,4665.29 6064.13,4665.29 6064.13,4645.29
  lines w12: 6026,3716.12 9906.95,3716.12 ; 6026,4691.12 9906.95,4691.12 ; 6317.44,3641.12 6317.44,4766.12 ; 6652.35,3641.12 6652.35,4766.12 ; 7341.16,3641.12 7341.16,4766.12 ; 7610.1,3641.12 7610.1,4766.12 ; 7993,3641.12 7993,4766.12 ; 8752.77,3641.12 8752.77,4766.12 ; 9309.62,3641.12 9309.62,4766.12 ; 6026,3641.12 9906.95,3641.12 9906.95,4766.12 6026,4766.12 6026,3641.12
  text "Symbol" at 6071,4713.62 h36
  text "Quantity" at 6339.94,4713.62 h36
  text "Finished Hole Size" at 6674.85,4713.62 h36
  text "Plated" at 7363.66,4713.62 h36
  text "Hole Type" at 7632.6,4713.62 h36
  text "Drill Layer Pair" at 8015.5,4713.62 h36
  text "Hole Tolerance" at 8775.27,4713.62 h36
  text "Hole Length" at 9332.12,4713.62 h36
  text "6" at 6339.94,4638.62 h30
  text "35.43mil (0.900mm)" at 6674.85,4638.62 h30
  text "NPTH" at 7363.66,4638.62 h30
  text "Round" at 7632.6,4638.62 h30
  text "Top Layer - Bottom Layer" at 8015.5,4638.62 h30
  text "-" at 9332.12,4638.62 h30
  text "4" at 6339.94,4563.62 h30
  text "125.00mil (3.175mm)" at 6674.85,4563.62 h30
  text "NPTH" at 7363.66,4563.62 h30
  text "Round" at 7632.6,4563.62 h30
  text "Top Layer - Bottom Layer" at 8015.5,4563.62 h30
  text "-" at 9332.12,4563.62 h30
  text "9" at 6339.94,4488.62 h30
  text "7.87mil (0.200mm)" at 6674.85,4488.62 h30
  text "PTH" at 7363.66,4488.62 h30
  text "Round" at 7632.6,4488.62 h30
  text "Top Layer - Bottom Layer" at 8015.5,4488.62 h30
  text "-" at 9332.12,4488.62 h30
  text "211" at 6339.94,4413.62 h30
  text "12.00mil (0.305mm)" at 6674.85,4413.62 h30
  text "PTH" at 7363.66,4413.62 h30
  text "Round" at 7632.6,4413.62 h30
  text "Top Layer - Bottom Layer" at 8015.5,4413.62 h30
  text "-" at 9332.12,4413.62 h30
  text "17" at 6339.94,4338.62 h30
  text "20.00mil (0.508mm)" at 6674.85,4338.62 h30
  text "PTH" at 7363.66,4338.62 h30
  text "Round" at 7632.6,4338.62 h30
  text "Top Layer - Bottom Layer" at 8015.5,4338.62 h30
  text "-" at 9332.12,4338.62 h30
  text "72" at 6339.94,4263.62 h30
  text "40.00mil (1.016mm)" at 6674.85,4263.62 h30
  text "PTH" at 7363.66,4263.62 h30
  text "Round" at 7632.6,4263.62 h30
  text "Top Layer - Bottom Layer" at 8015.5,4263.62 h30
  text "-" at 9332.12,4263.62 h30
  text "58" at 6339.94,4188.62 h30
  text "40.16mil (1.020mm)" at 6674.85,4188.62 h30
  text "PTH" at 7363.66,4188.62 h30
  text "Round" at 7632.6,4188.62 h30
  text "Top Layer - Bottom Layer" at 8015.5,4188.62 h30
  text "-" at 9332.12,4188.62 h30
  text "20" at 6339.94,4113.62 h30
  text "45.28mil (1.150mm)" at 6674.85,4113.62 h30
  text "PTH" at 7363.66,4113.62 h30
  text "Round" at 7632.6,4113.62 h30
  text "Top Layer - Bottom Layer" at 8015.5,4113.62 h30
  text "-" at 9332.12,4113.62 h30
  text "1" at 6339.94,4038.62 h30
  text "59.06mil (1.500mm)" at 6674.85,4038.62 h30
  text "PTH" at 7363.66,4038.62 h30
  text "Round" at 7632.6,4038.62 h30
  text "Top Layer - Bottom Layer" at 8015.5,4038.62 h30
  text "-" at 9332.12,4038.62 h30
  text "4" at 6339.94,3963.62 h30
  text "62.99mil (1.600mm)" at 6674.85,3963.62 h30
  text "PTH" at 7363.66,3963.62 h30
  text "Round" at 7632.6,3963.62 h30
  text "Top Layer - Bottom Layer" at 8015.5,3963.62 h30
  text "-" at 9332.12,3963.62 h30
  text "1" at 6339.94,3888.62 h30
  text "21.00mil (0.533mm)" at 6674.85,3888.62 h30
  text "NPTH" at 7363.66,3888.62 h30
  text "Slot" at 7632.6,3888.62 h30
  text "Top Layer - Bottom Layer" at 8015.5,3888.62 h30
  text "87.00mil (2.210mm)" at 9332.12,3888.62 h30
  text "2" at 6339.94,3813.62 h30
  text "21.00mil (0.533mm)" at 6674.85,3813.62 h30
  text "NPTH" at 7363.66,3813.62 h30
  text "Slot" at 7632.6,3813.62 h30
  text "Top Layer - Bottom Layer" at 8015.5,3813.62 h30
  text "162.00mil (4.115mm)" at 9332.12,3813.62 h30
  text "2" at 6339.94,3738.62 h30
  text "23.62mil (0.600mm)" at 6674.85,3738.62 h30
  text "PTH" at 7363.66,3738.62 h30
  text "Slot" at 7632.6,3738.62 h30
  text "Top Layer - Bottom Layer" at 8015.5,3738.62 h30
  text "51.18mil (1.300mm)" at 9332.12,3738.62 h30
  text "407 Total" at 6339.94,3663.62 h30
  text "Slot definitions :" at 6071,3581.13 h30
  text "Routed Path Length" at 6601.34,3581.13 h30
  text "= Calculated from tool start centre position to tool end centre position." at 7166.68,3581.13 h30
  text "Hole Length" at 6601.34,3521.14 h30
  text "= Routed Path Length + Tool Size = Slot length as defined in the PCB layout" at 6961.74,3521.14 h30
  text ".Layer_Name" at 527,-1523.49 h30
M17 Embedded Cavity:
  text ".Layer_Name" at 527,-1523.49 h30
M18 Embedded Assembly:
  text ".Layer_Name" at 527,-1523.49 h30
M19 Embedded Keepout:
  text ".Layer_Name" at 527,-1523.49 h30

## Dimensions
0,0 to 2300,0 on M2 Board Dimensions
0,0 to 0,4195 on M2 Board Dimensions
-50,-1065 to 950,-1065 on M2 Board Dimensions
